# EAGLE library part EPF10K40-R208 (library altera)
EPF10K40 FLEX 10K family
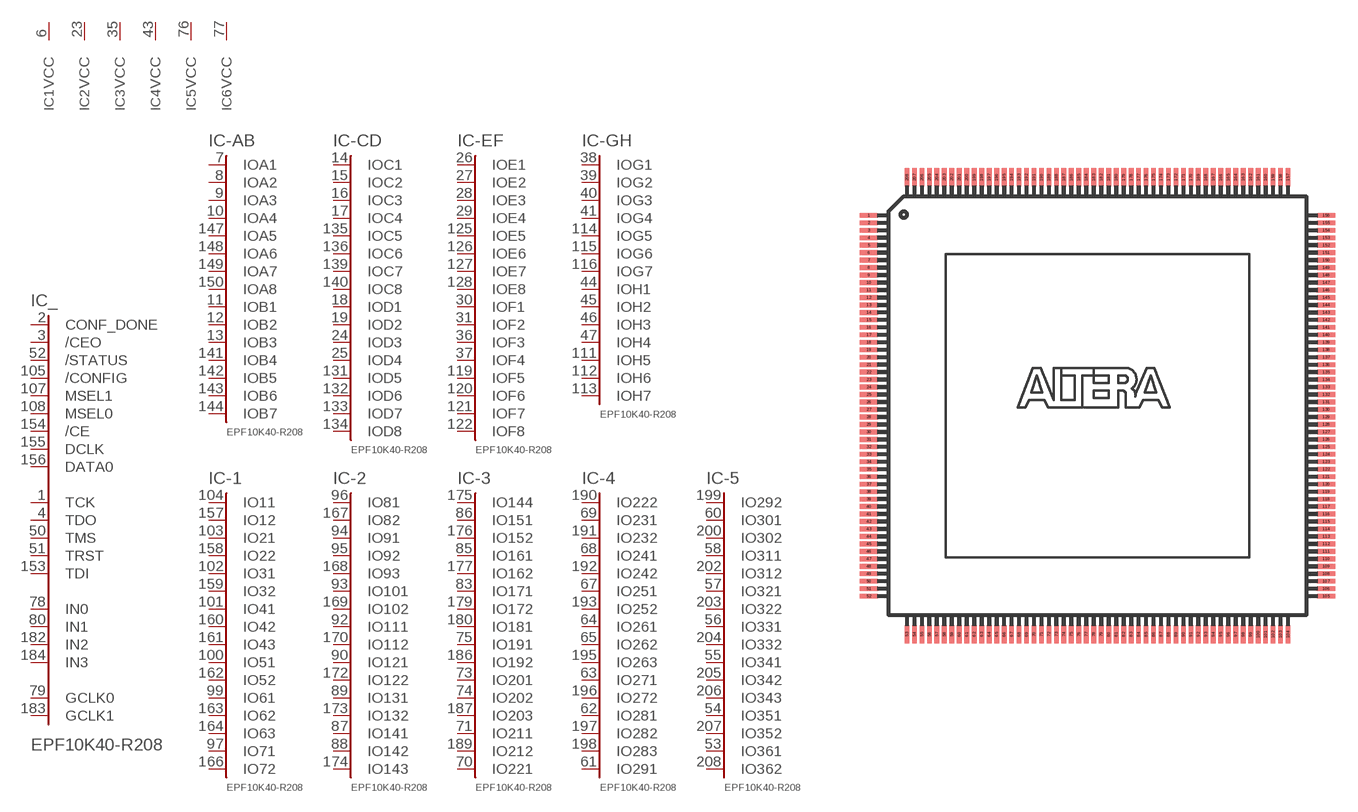
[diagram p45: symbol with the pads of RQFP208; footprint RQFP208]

Designator prefix IC; gates _=100R240C -AB=A8B7 -CD=C8D8 -EF=E8F8 -GH=G7H7 -1=72-40R -2=143-40R -3=221-40R -4=291-40R -5=362-40R 1=VCCINT 2=VCCINT 3=VCCINT 4=VCCINT 5=VCCINT 6=VCCINT 7=VCCINT 8=VCCINT 9=VCCINT 10=VCCINT 11=VCCINT 12=VCCINT 13=VCCIO 14=VCCIO 15=VCCIO 16=VCCIO 17=VCCIO 18=VCCIO 19=VCCIO 20=VCCIO 21=VCCIO 22=VCCIO 23=VCCIO 24=VCCIO 25=VCCIO 26=VCCIO 27=GNDINT 28=GNDINT 29=GNDINT 30=GNDINT 31=GNDINT 32=GNDINT 33=GNDINT 34=GNDINT 35=GNDINT 36=GNDIO 37=GNDIO 38=GNDIO 39=GNDIO 40=GNDIO 41=GNDIO 42=GNDIO 43=GNDIO 44=GNDIO 45=GNDIO 46=GNDIO 47=GNDIO

## EPF10K40-R208 (MPN: EPF10K40RC208-3; OC_FARNELL: unknown; OC_NEWARK: 51R9013)  [RQFP208]
1  _:TCK
2  _:CONF_DONE  in
3  _:/CEO  in
4  _:TDO
5  13:VCCIO  pwr
6  1:VCC  pwr
7  -AB:IOA1
8  -AB:IOA2
9  -AB:IOA3
10  -AB:IOA4
11  -AB:IOB1
12  -AB:IOB2
13  -AB:IOB3
14  -CD:IOC1
15  -CD:IOC2
16  -CD:IOC3
17  -CD:IOC4
18  -CD:IOD1
19  -CD:IOD2
20  36:GNDIO  pwr
21  27:GND  pwr
22  14:VCCIO  pwr
23  2:VCC  pwr
24  -CD:IOD3
25  -CD:IOD4
26  -EF:IOE1
27  -EF:IOE2
28  -EF:IOE3
29  -EF:IOE4
30  -EF:IOF1
31  -EF:IOF2
32  37:GNDIO  pwr
33  28:GND  pwr
34  15:VCCIO  pwr
35  3:VCC  pwr
36  -EF:IOF3
37  -EF:IOF4
38  -GH:IOG1
39  -GH:IOG2
40  -GH:IOG3
41  -GH:IOG4
42  16:VCCIO  pwr
43  4:VCC  pwr
44  -GH:IOH1
45  -GH:IOH2
46  -GH:IOH3
47  -GH:IOH4
48  38:GNDIO  pwr
49  29:GND  pwr
50  _:TMS
51  _:TRST
52  _:/STATUS  in
53  -5:IO361
54  -5:IO351
55  -5:IO341
56  -5:IO331
57  -5:IO321
58  -5:IO311
59  39:GNDIO  pwr
60  -5:IO301
61  -4:IO291
62  -4:IO281
63  -4:IO271
64  -4:IO261
65  -4:IO262
66  17:VCCIO  pwr
67  -4:IO251
68  -4:IO241
69  -4:IO231
70  -3:IO221
71  -3:IO211
72  40:GNDIO  pwr
73  -3:IO201
74  -3:IO202
75  -3:IO191
76  5:VCC  pwr
77  6:VCC  pwr
78  _:IN0  in
79  _:GCLK0  in
80  _:IN1  in
81  30:GND  pwr
82  31:GND  pwr
83  -3:IO171
84  18:VCCIO  pwr
85  -3:IO161
86  -3:IO151
87  -2:IO141
88  -2:IO142
89  -2:IO131
90  -2:IO121
91  41:GNDIO  pwr
92  -2:IO111
93  -2:IO101
94  -2:IO91
95  -2:IO92
96  -2:IO81
97  -1:IO71
98  19:VCCIO  pwr
99  -1:IO61
100  -1:IO51
101  -1:IO41
102  -1:IO31
103  -1:IO21
104  -1:IO11
105  _:/CONFIG  in
106  7:VCC  pwr
107  _:MSEL1  in
108  _:MSEL0  in
109  8:VCC  pwr
110  20:VCCIO  pwr
111  -GH:IOH5
112  -GH:IOH6
113  -GH:IOH7
114  -GH:IOG5
115  -GH:IOG6
116  -GH:IOG7
117  9:VCC  pwr
118  21:VCCIO  pwr
119  -EF:IOF5
120  -EF:IOF6
121  -EF:IOF7
122  -EF:IOF8
123  32:GND  pwr
124  42:GNDIO  pwr
125  -EF:IOE5
126  -EF:IOE6
127  -EF:IOE7
128  -EF:IOE8
129  33:GND  pwr
130  43:GNDIO  pwr
131  -CD:IOD5
132  -CD:IOD6
133  -CD:IOD7
134  -CD:IOD8
135  -CD:IOC5
136  -CD:IOC6
137  10:VCC  pwr
138  22:VCCIO  pwr
139  -CD:IOC7
140  -CD:IOC8
141  -AB:IOB4
142  -AB:IOB5
143  -AB:IOB6
144  -AB:IOB7
145  11:VCC  pwr
146  23:VCCIO  pwr
147  -AB:IOA5
148  -AB:IOA6
149  -AB:IOA7
150  -AB:IOA8
151  34:GND  pwr
152  44:GNDIO  pwr
153  _:TDI
154  _:/CE  in
155  _:DCLK  in
156  _:DATA0  in
157  -1:IO12
158  -1:IO22
159  -1:IO32
160  -1:IO42
161  -1:IO43
162  -1:IO52
163  -1:IO62
164  -1:IO63
165  24:VCCIO  pwr
166  -1:IO72
167  -2:IO82
168  -2:IO93
169  -2:IO102
170  -2:IO112
171  45:GNDIO  pwr
172  -2:IO122
173  -2:IO132
174  -2:IO143
175  -3:IO144
176  -3:IO152
177  -3:IO162
178  25:VCCIO  pwr
179  -3:IO172
180  -3:IO181
181  12:VCC  pwr
182  _:IN2  in
183  _:GCLK1  in
184  _:IN3  in
185  35:GND  pwr
186  -3:IO192
187  -3:IO203
188  46:GNDIO  pwr
189  -3:IO212
190  -4:IO222
191  -4:IO232
192  -4:IO242
193  -4:IO252
194  26:VCCIO  pwr
195  -4:IO263
196  -4:IO272
197  -4:IO282
198  -4:IO283
199  -5:IO292
200  -5:IO302
201  47:GNDIO  pwr
202  -5:IO312
203  -5:IO322
204  -5:IO332
205  -5:IO342
206  -5:IO343
207  -5:IO352
208  -5:IO362

## Footprint RQFP208 (pad centres in mm)
Power Quad Flat Pack
smd 1.2 x 0.32: 1 -15.3,12.75; 2 -15.3,12.25; 3 -15.3,11.75; 4 -15.3,11.25; 5 -15.3,10.75; 6 -15.3,10.25; 7 -15.3,9.75; 8 -15.3,9.25; 9 -15.3,8.75; 10 -15.3,8.25; 11 -15.3,7.75; 12 -15.3,7.25; 13 -15.3,6.75; 14 -15.3,6.25; 15 -15.3,5.75; 16 -15.3,5.25; 17 -15.3,4.75; 18 -15.3,4.25; 19 -15.3,3.75; 20 -15.3,3.25; 21 -15.3,2.75; 22 -15.3,2.25; 23 -15.3,1.75; 24 -15.3,1.25; 25 -15.3,0.75; 26 -15.3,0.25; 27 -15.3,-0.25; 28 -15.3,-0.75; 29 -15.3,-1.25; 30 -15.3,-1.75; 31 -15.3,-2.25; 32 -15.3,-2.75; 33 -15.3,-3.25; 34 -15.3,-3.75; 35 -15.3,-4.25; 36 -15.3,-4.75; 37 -15.3,-5.25; 38 -15.3,-5.75; 39 -15.3,-6.25; 40 -15.3,-6.75; 41 -15.3,-7.25; 42 -15.3,-7.75; 43 -15.3,-8.25; 44 -15.3,-8.75; 45 -15.3,-9.25; 46 -15.3,-9.75; 47 -15.3,-10.25; 48 -15.3,-10.75; 49 -15.3,-11.25; 50 -15.3,-11.75; 51 -15.3,-12.25; 52 -15.3,-12.75; 105 15.3,-12.75; 106 15.3,-12.25; 107 15.3,-11.75; 108 15.3,-11.25; 109 15.3,-10.75; 110 15.3,-10.25; 111 15.3,-9.75; 112 15.3,-9.25; 113 15.3,-8.75; 114 15.3,-8.25; 115 15.3,-7.75; 116 15.3,-7.25; 117 15.3,-6.75; 118 15.3,-6.25; 119 15.3,-5.75; 120 15.3,-5.25; 121 15.3,-4.75; 122 15.3,-4.25; 123 15.3,-3.75; 124 15.3,-3.25; 125 15.3,-2.75; 126 15.3,-2.25; 127 15.3,-1.75; 128 15.3,-1.25; 129 15.3,-0.75; 130 15.3,-0.25; 131 15.3,0.25; 132 15.3,0.75; 133 15.3,1.25; 134 15.3,1.75; 135 15.3,2.25; 136 15.3,2.75; 137 15.3,3.25; 138 15.3,3.75; 139 15.3,4.25; 140 15.3,4.75; 141 15.3,5.25; 142 15.3,5.75; 143 15.3,6.25; 144 15.3,6.75; 145 15.3,7.25; 146 15.3,7.75; 147 15.3,8.25; 148 15.3,8.75; 149 15.3,9.25; 150 15.3,9.75; 151 15.3,10.25; 152 15.3,10.75; 153 15.3,11.25; 154 15.3,11.75; 155 15.3,12.25; 156 15.3,12.75
smd 0.32 x 1.2: 53 -12.75,-15.3; 54 -12.25,-15.3; 55 -11.75,-15.3; 56 -11.25,-15.3; 57 -10.75,-15.3; 58 -10.25,-15.3; 59 -9.75,-15.3; 60 -9.25,-15.3; 61 -8.75,-15.3; 62 -8.25,-15.3; 63 -7.75,-15.3; 64 -7.25,-15.3; 65 -6.75,-15.3; 66 -6.25,-15.3; 67 -5.75,-15.3; 68 -5.25,-15.3; 69 -4.75,-15.3; 70 -4.25,-15.3; 71 -3.75,-15.3; 72 -3.25,-15.3; 73 -2.75,-15.3; 74 -2.25,-15.3; 75 -1.75,-15.3; 76 -1.25,-15.3; 77 -0.75,-15.3; 78 -0.25,-15.3; 79 0.25,-15.3; 80 0.75,-15.3; 81 1.25,-15.3; 82 1.75,-15.3; 83 2.25,-15.3; 84 2.75,-15.3; 85 3.25,-15.3; 86 3.75,-15.3; 87 4.25,-15.3; 88 4.75,-15.3; 89 5.25,-15.3; 90 5.75,-15.3; 91 6.25,-15.3; 92 6.75,-15.3; 93 7.25,-15.3; 94 7.75,-15.3; 95 8.25,-15.3; 96 8.75,-15.3; 97 9.25,-15.3; 98 9.75,-15.3; 99 10.25,-15.3; 100 10.75,-15.3; 101 11.25,-15.3; 102 11.75,-15.3; 103 12.25,-15.3; 104 12.75,-15.3; 157 12.75,15.3; 158 12.25,15.3; 159 11.75,15.3; 160 11.25,15.3; 161 10.75,15.3; 162 10.25,15.3; 163 9.75,15.3; 164 9.25,15.3; 165 8.75,15.3; 166 8.25,15.3; 167 7.75,15.3; 168 7.25,15.3; 169 6.75,15.3; 170 6.25,15.3; 171 5.75,15.3; 172 5.25,15.3; 173 4.75,15.3; 174 4.25,15.3; 175 3.75,15.3; 176 3.25,15.3; 177 2.75,15.3; 178 2.25,15.3; 179 1.75,15.3; 180 1.25,15.3; 181 0.75,15.3; 182 0.25,15.3; 183 -0.25,15.3; 184 -0.75,15.3; 185 -1.25,15.3; 186 -1.75,15.3; 187 -2.25,15.3; 188 -2.75,15.3; 189 -3.25,15.3; 190 -3.75,15.3; 191 -4.25,15.3; 192 -4.75,15.3; 193 -5.25,15.3; 194 -5.75,15.3; 195 -6.25,15.3; 196 -6.75,15.3; 197 -7.25,15.3; 198 -7.75,15.3; 199 -8.25,15.3; 200 -8.75,15.3; 201 -9.25,15.3; 202 -9.75,15.3; 203 -10.25,15.3; 204 -10.75,15.3; 205 -11.25,15.3; 206 -11.75,15.3; 207 -12.25,15.3; 208 -12.75,15.3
